(* Logix 5000 project; controller GSC vendor 1 type 14 code 54 rev 19.11; software revision 19.01 *)

TASK MainTask (continuous, watchdog 500 ms) : MainProgram

MODULES
   Local : vendor 1 type 14 code 54 (ICP 0, rev 19.11)
      GSC : vendor 309 type 12 code 5003 (ICP 1, rev 2.1, Output RPI 5 ms)
END_MODULES

TYPE GSCBLOCKSTATUS :   // This shows all blocks that were used by the module
STRUCT
   Read : INT;   // Number of blocks read by the module
   Write : INT;   // Number of blocks written by the module
   Parse : INT;   // Number of blocks parsed by the module
   Err : INT;   // Number of block transfer errors
END_STRUCT
END_TYPE

TYPE GSCCLOCKTYPE :   // Allows read/write of clock value between the module and processor
STRUCT
   Read : BOOL;   // Reads current time from the module
   Write : BOOL;   // Writes current time from the module
   Config : GSCDATETIME;   // Date and time configuration read or written between the module and processor
END_STRUCT
END_TYPE

TYPE GSCCONTROL :   // Ladder send special blocks to request the module to perform the request
STRUCT
   Warmboot : BOOL;   // Performs a warm boot operation on the module (software reset).
   Coldboot : BOOL;   // Performs a cold boot operation on the module (hardware and software reset).
   ConfigDone : BOOL;   // Confirms the module received its configuration from ladder logic
END_STRUCT
END_TYPE

TYPE GSCDATA :   // The following contains the data read in on the port and to be written out the port.
STRUCT
   Port1 : GSCPORTDATA;   // Port 1 data
   Port2 : GSCPORTDATA;   // Port 2 data
END_STRUCT
END_TYPE

TYPE GSCDATETIME :   // Stores the date and time value
STRUCT
   Year : DINT;
   Month : DINT;
   Day : DINT;
   Hour : DINT;
   Minute : DINT;
   Seconds : DINT;
END_STRUCT
END_TYPE

TYPE GSCERRORWORD :   // Bit coded error word for configuration and overflow error for MVI56-GSC module.
STRUCT
   Cfg_type : BOOL;   // Bit 0, type field configuration error
   Cfg_Baud : BOOL;   // Bit 1, baud rate field configuration error
   Cfg_Parity : BOOL;   // Bit 2, parity field configuration error
   Cfg_DataBits : BOOL;   // Bit 3, data bit field configuration error
   Cfg_StopBits : BOOL;   // Bit 4, stop bit field configuration error
   Cfg_Handshake : BOOL;   // Bit 5, handshaking field configuration error
   Cfg_RTermcount : BOOL;   // Bit 6, receive termination character count field configuration error
   Cfg_RPacketLen : BOOL;   // Bit 7, receive packet length field configuration error
   Cfg_RTimeout : BOOL;   // Bit 8, receive message timeout field configuration error
   Cfg_RDelay : BOOL;   // Bit 9, receive intercharacter delay field configuration error
   Cfg_WTimeout : BOOL;   // Bit 10, write message timeout field configuration error
   Resv_Bit11 : BOOL;   // Bit 11
   Resv_Bit12 : BOOL;   // Bit 12
   Resv_Bit13 : BOOL;   // Bit 13
   Resv_Bit14 : BOOL;   // Bit 14
   Err_ROverflow : BOOL;   // Bit 15, receive overflow error
END_STRUCT
END_TYPE

TYPE GSCETHERNET :   // Stores the MVI56E-GSC IP settings
STRUCT
   IP : INT[4];
   Netmask : INT[4];
   Gateway : INT[4];
END_STRUCT
END_TYPE

TYPE GSCETHERNETTYPE :   // Allows read/write Ethernet settings between the module and processor
STRUCT
   Read : BOOL;   // Enable Ethernet configuration transfer from module to processor
   Write : BOOL;   // Enable Ethernet configuration transfer from processor to module
   Config : GSCETHERNET;
END_STRUCT
END_TYPE

TYPE GSCMODULEDEF :   // This defines the complete module tags
STRUCT
   CONFIG : GSCPORTCONFIG;   // Port configuration parameters
   DATA : GSCDATA;   // Port sent and received data
   STATUS : GSCSTATUS;   // Module status data and individual port status
   CONTROL : GSCCONTROL;   // Module control parameters
   UTIL : GSCUTIL;   // Tags used by the module
END_STRUCT
END_TYPE

TYPE GSCPORTCONFIG :   // Shows both ports configuration
STRUCT
   Port1 : GSCPORTCONFIGPARA;   // Port 1 configuration data
   Port2 : GSCPORTCONFIGPARA;   // Port 2 configuration data
END_STRUCT
END_TYPE

TYPE GSCPORTCONFIGPARA :   // The following are the configuration parameters for the port of the MVI56-GSC module.
STRUCT
   Enabled : INT;   // 0=Disable port, 1=Enable port
   Type : INT;   // Type of control used to flush data received on port
   Baudrate : INT;   // Baud rate for communications
   Parity : INT;   // Parity (0=none, 1=odd, 2=even, 3=mark, 4=space)
   DataBits : INT;   // Data bits (5, 6, 7, or 8)
   StopBits : INT;   // Stop bits (1 or 2)
   RTSOn : INT;   // RTS delay before sending data
   RTSOff : INT;   // RTS delay after sending message
   Handshaking : INT;   // Type of Handshaking (0=none, 1=RTSCTS, 2=DTRDSR,3=XONXOFF)
   RTermCnt : INT;   // Number of termination characters for received message for control
   RTermChar : SINT[12];   // Characters for termination control
   RPacketLen : INT;   // Fixed packet length value
   RTimeout : INT;   // Message timeout value for control
   RDelay : INT;   // Intercharacter timeout for control
   WTermCnt : INT;   // Not used
   WTermChar : SINT[12];   // Not used
   WPacketLen : INT;   // Not used
   WTimeout : INT;   // Timeout for sending a message out the port
   Spare : INT;   // Not used
   WMinDelay : INT;   // Minimum delay before transmitting message out port
END_STRUCT
END_TYPE

TYPE GSCPORTDATA :   // Individual port data
STRUCT
   ReadLength : INT;   // The length of character the port is rescieving
   ReadString : SINT[4096];   // Where received data will be displayed
   WriteLength : INT;   // The length of character the port is transmitting
   WDelay : INT;   // Number of milliseconds to wait between each character sent from the port
   WriteString : SINT[4096];   // Where sent data will be placed before it is sent
END_STRUCT
END_TYPE

TYPE GSCPORTSTAT :   // Port status Data
STRUCT
   RxState : INT;   // State of receive task
   RxCharCnt : INT;   // Number of characters received on port
   RxMsgCnt : INT;   // Number of messages received on port
   TxState : INT;   // State of transmit task
   TxCharCnt : INT;   // Number of characters transmitted on port
   TxMsgCnt : INT;   // Number of messages transmitted on port
   ErrorWord : GSCERRORWORD;   // Error/Configuration Word for port
END_STRUCT
END_TYPE

TYPE GSCSTATUS :   // Module Status data
STRUCT
   PassCnt : INT;   // Program cycle counter for module
   Product : INT[2];   // Product code for module (GSC)
   Rev : INT[2];   // Revision level of module's code
   OP : INT[2];   // Operating system version for module
   Run : INT[2];   // Run number for module
   BlockStatus : GSCBLOCKSTATUS;   // Data block transfer statistics
   Port1 : GSCPORTSTAT;   // Status for port1
   Port2 : GSCPORTSTAT;   // Status for port 2
END_STRUCT
END_TYPE

TYPE GSCUTIL :   // Used by the module for block hand shaking
STRUCT
   LastRead : SINT;   // This is used to read the input image from the processor
   LastWrite : SINT;   // This is used to write the output image to the processor
   BackplaneFail : INT;   // This is used to control number of backplane failures before module stops communicating on both gsc ports
   P1WriteLast : INT;   // Port 1 last write data in the array
   P2Writelast : INT;   // Port 2 last data in the array
   P1ArrayIndex : INT;   // This is the index reference within the read or write data array for port1
   P2ArrayIndex : INT;   // This is the index reference within the read or write data array for port 2
   P1RSindex : INT;   // used when more than 200 characters are received on the port 1
   P2RSindex : INT;   // used when more than 200 characters are received on the port 2
   P1Temp1 : INT;   // This temp parameter for port 1 is used to copy SINT to an INT in order to read a vlaue is higher than 127 characters
   P2Temp2 : INT;   // This temp parameter for port 2 is used to copy SINT to an INT in order to read a vlaue is higher than 127 characters
   Scratch1 : INT;   // Used to calculate number of characters read by the port
   Scratch2 : INT;   // Used to calculate number of characters read by the port
END_STRUCT
END_TYPE

ADD_ON_INSTRUCTION AOI56EGSC_OPTIONAL   (* revision 1.1 *)
// MVI56E-GSC Optional Add-On Ethernet/Clock
// Revision note:
// Added viewing capability for the Add_On Instruction
VAR_IN_OUT
   MVI56EGSCEthernet : GSCETHERNETTYPE; {required}   // MVI56E-GSC Rev2 Ethernet Settings
   MVI56EGSCClock : GSCCLOCKTYPE; {required}   // MVI56E-GSC Rev2 Clock Settings
   ReadEthernetMSG : MESSAGE; {required}   // Read Ethernet Settings Message
   WriteEthernetMSG : MESSAGE; {required}   // Write Ethernet Settings Message
   ReadClockMSG : MESSAGE; {required}   // Read Clock Settings Message
   WriteClockMSG : MESSAGE; {required}   // Write Clock Settings Message
END_VAR

ROUTINE Logic   (* ladder *)
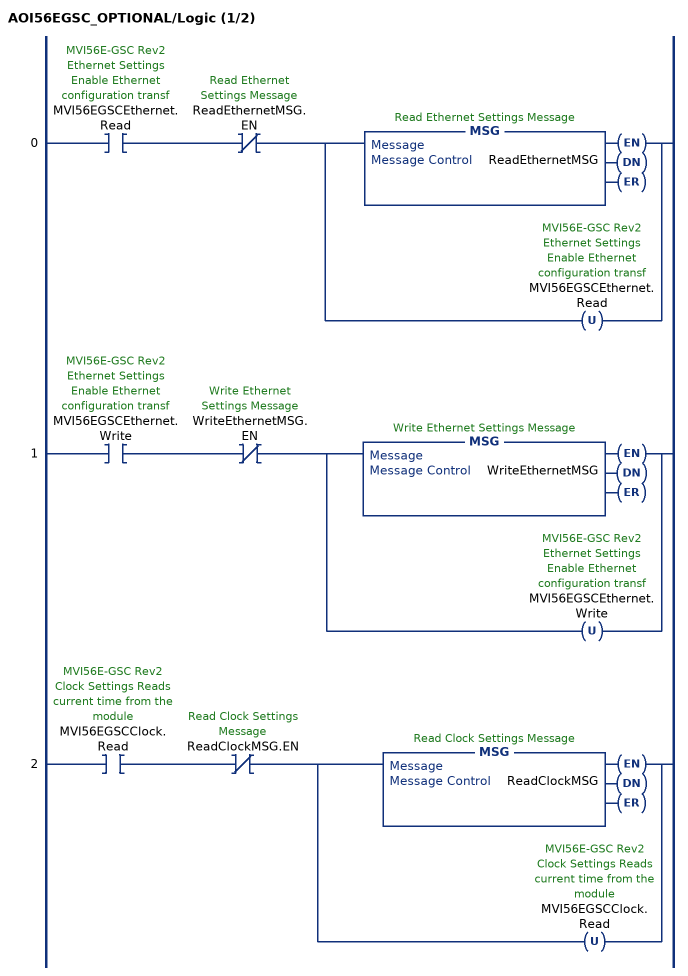
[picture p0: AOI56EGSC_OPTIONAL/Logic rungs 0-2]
   0: XIC(MVI56EGSCEthernet.Read)XIO(ReadEthernetMSG.EN)[MSG(ReadEthernetMSG) ,OTU(MVI56EGSCEthernet.Read) ];
   1: XIC(MVI56EGSCEthernet.Write)XIO(WriteEthernetMSG.EN)[MSG(WriteEthernetMSG) ,OTU(MVI56EGSCEthernet.Write) ];
   2: XIC(MVI56EGSCClock.Read)XIO(ReadClockMSG.EN)[MSG(ReadClockMSG) ,OTU(MVI56EGSCClock.Read) ];
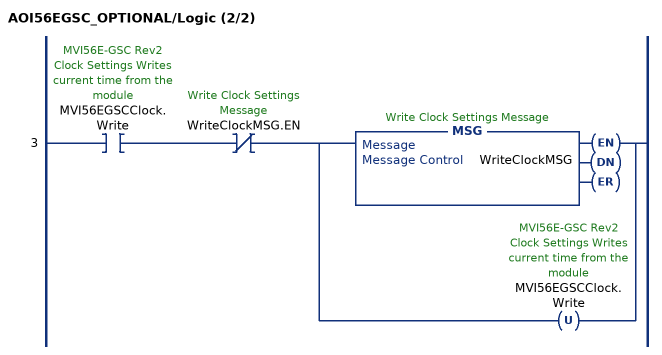
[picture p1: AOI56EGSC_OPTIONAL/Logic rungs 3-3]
   3: XIC(MVI56EGSCClock.Write)XIO(WriteClockMSG.EN)[MSG(WriteClockMSG) ,OTU(MVI56EGSCClock.Write) ];
END_ROUTINE
END_ADD_ON_INSTRUCTION

ADD_ON_INSTRUCTION AOI56GSC   (* revision 1.9, vendor ProSoft Technology Inc., ExecutePrescan *)
// Add-On For MVI56GSC and MVI56EGSC Modules.
// Revision note:
// 7/6/17
// Minor fix to FLL instruction
// 6/7/16
// Confirmed fix regarding 'Copy' length on the GSC.UTIL.PxTempx
// Help:
// 05/09/13
// AOI was fixed so that GSC.UTIL.Backplane.Fail parameter was affecting the intercharacter delay parameter in the module
VAR_IN_OUT
   Connection_Input : SINT[500]; {required}
   Connection_Output : SINT[496]; {required}
   GSC : GSCMODULEDEF; {required}
END_VAR
VAR
   MJFAULTS : DINT[12];
   ONS_Config : BOOL;
END_VAR

ROUTINE Logic   (* ladder *)
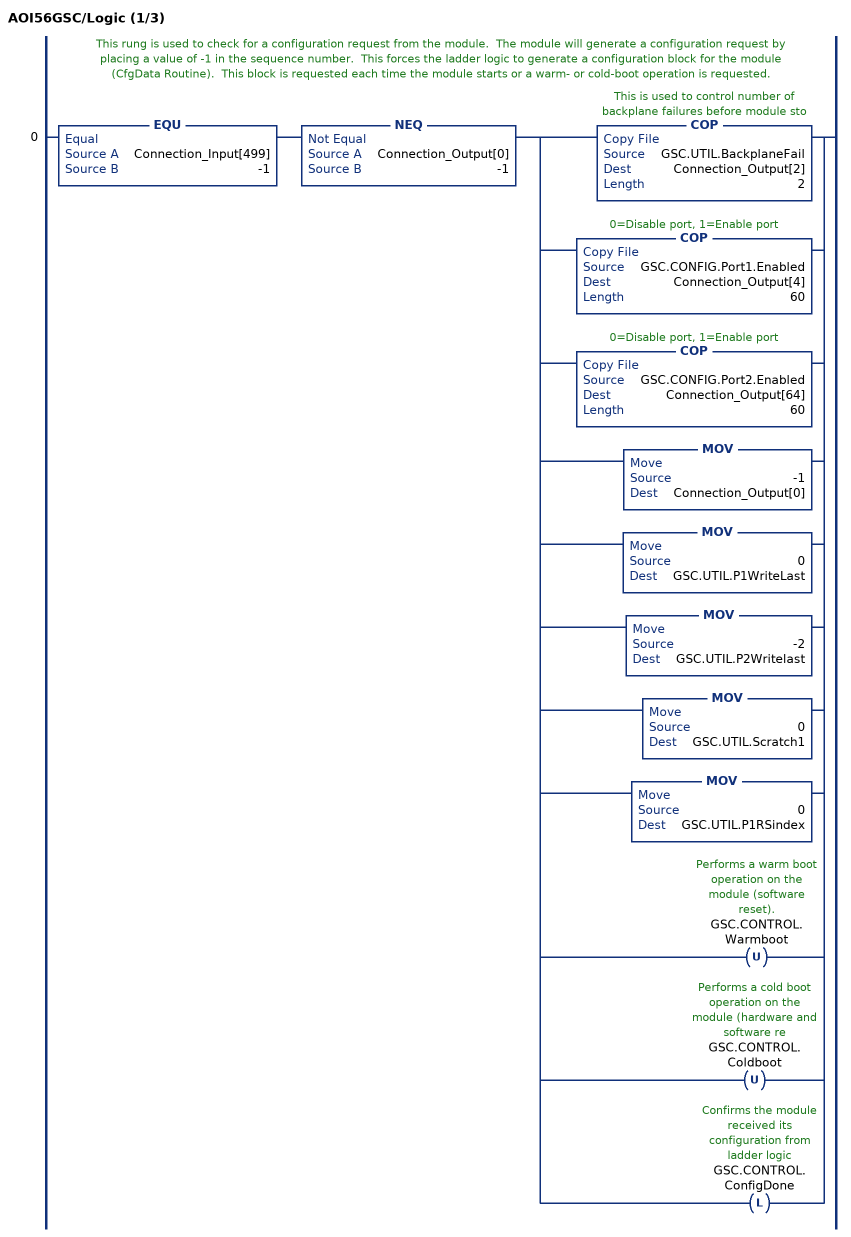
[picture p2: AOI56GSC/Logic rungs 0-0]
   // This rung is used to check for a configuration request from the module.  The module will generate a configuration request by placing a value of -1 in the sequence number.  This forces the ladder logic to generate a configuration block for the module (CfgData Routine).  This block is requested each time the module starts or a warm- or cold-boot operation is requested.
   0: EQU(Connection_Input[499],-1)NEQ(Connection_Output[0],-1)[COP(GSC.UTIL.BackplaneFail,Connection_Output[2],2) ,COP(GSC.CONFIG.Port1.Enabled,Connection_Output[4],60) ,COP(GSC.CONFIG.Port2.Enabled,Connection_Output[64],60) ,MOV(-1,Connection_Output[0]) ,MOV(0,GSC.UTIL.P1WriteLast) ,MOV(-2,GSC.UTIL.P2Writelast) ,MOV(0,GSC.UTIL.Scratch1) ,MOV(0,GSC.UTIL.P1RSindex) ,OTU(GSC.CONTROL.Warmboot) ,OTU(GSC.CONTROL.Coldboot) ,OTL(GSC.CONTROL.ConfigDone) ];
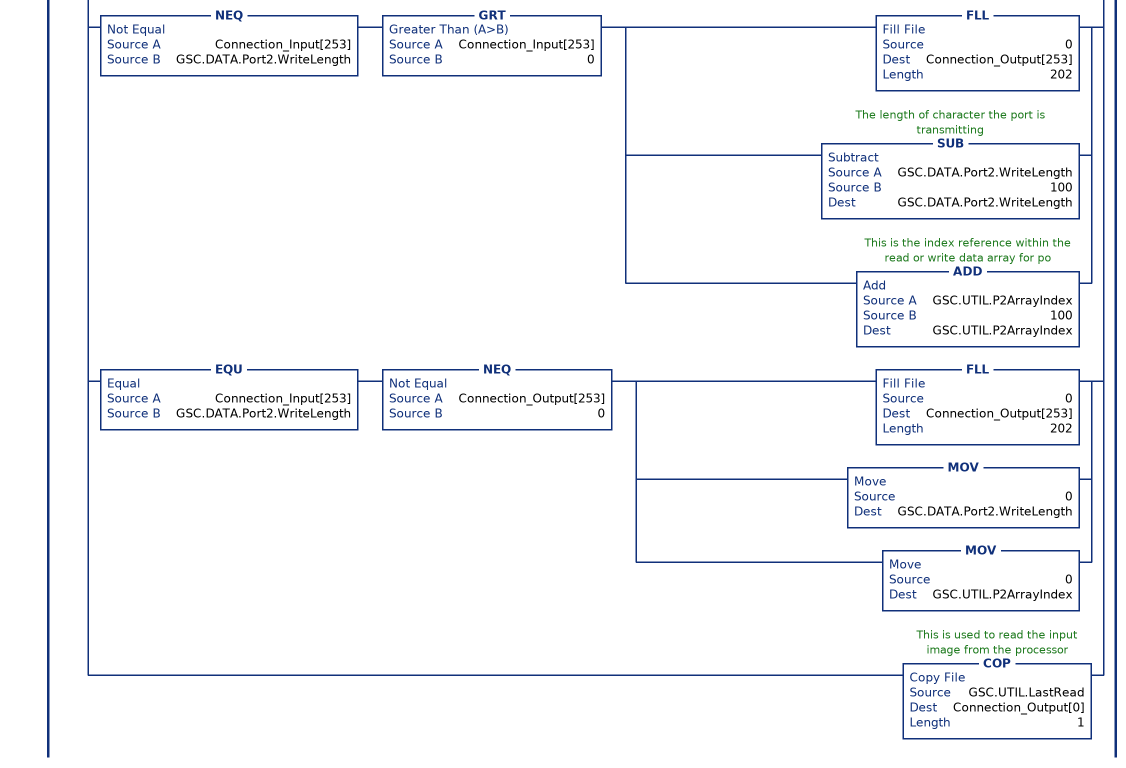
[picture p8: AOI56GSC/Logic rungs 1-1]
   // This rung is executed when a new data block is received from the module.  These blocks will have a sequence number range of 0 to 127.  When a new block is received, the ProcessBlock routine is executed to handle the newly received data.
   1: NEQ(Connection_Input[499],GSC.UTIL.LastRead)NEQ(Connection_Input[499],-1)XIO(GSC.CONTROL.Warmboot)XIO(GSC.CONTROL.Coldboot)[COP(Connection_Input[499],GSC.UTIL.LastRead,1) ,GEQ(GSC.UTIL.LastRead,0) [COP(Connection_Input[210],GSC.STATUS.PassCnt,1) ,COP(Connection_Input[1],GSC.UTIL.P1Temp1,1) ,COP(Connection_Input[251],GSC.UTIL.P2Temp2,1) ,COP(Connection_Input[212],GSC.STATUS.Product[0],8) ,COP(Connection_Input[228],GSC.STATUS.BlockStatus.Read,4) ,COP(Connection_Input[236],GSC.STATUS.Port1.RxState,6) ,COP(Connection_Input[248],GSC.STATUS.Port1.ErrorWord,1) ,COP(Connection_Input[456],GSC.STATUS.Port2.RxState,6) ,COP(Connection_Input[468],GSC.STATUS.Port2.ErrorWord,1) ,EQU(GSC.UTIL.P1Temp1,-1) LES(GSC.UTIL.P1RSindex,20) [COP(Connection_Input[5],GSC.DATA.Port1.ReadString[GSC.UTIL.P1RSindex*200],200) ,ADD(1,GSC.UTIL.P1RSindex,GSC.UTIL.P1RSindex) ,MUL(GSC.UTIL.P1RSindex,200,GSC.UTIL.Scratch1) ] ,GRT(GSC.UTIL.P1Temp1,0) [MOV(0,GSC.DATA.Port1.ReadLength) ,COP(Connection_Input[5],GSC.DATA.Port1.ReadString[GSC.UTIL.P1RSindex*200],200) ,ADD(GSC.UTIL.P1Temp1,GSC.UTIL.Scratch1,GSC.DATA.Port1.ReadLength) ,MOV(0,GSC.UTIL.P1RSindex) ,MOV(0,GSC.UTIL.Scratch1) ] ,EQU(GSC.UTIL.P2Temp2,-1) LES(GSC.UTIL.P2RSindex,20) [COP(Connection_Input[255],GSC.DATA.Port2.ReadString[GSC.UTIL.P2RSindex*200],200) ,ADD(1,GSC.UTIL.P2RSindex,GSC.UTIL.P2RSindex) ,MUL(GSC.UTIL.P2RSindex,200,GSC.UTIL.Scratch2) ] ,GRT(GSC.UTIL.P2Temp2,0) [MOV(0,GSC.DATA.Port2.ReadLength) ,COP(Connection_Input[255],GSC.DATA.Port2.ReadString[GSC.UTIL.P2RSindex*200],200) ,ADD(GSC.UTIL.P2Temp2,GSC.UTIL.Scratch2,GSC.DATA.Port2.ReadLength) ,MOV(0,GSC.UTIL.P2RSindex) ,MOV(0,GSC.UTIL.Scratch2) ] ] ,XIC(GSC.CONTROL.ConfigDone) [FLL(0,Connection_Output[1],495) ,OTU(GSC.CONTROL.ConfigDone) ] ,GRT(GSC.DATA.Port1.WriteLength,100) LEQ(GSC.DATA.Port1.WriteLength,4096) [COP(GSC.DATA.Port1.WriteString[GSC.UTIL.P1ArrayIndex],Connection_Output[5],100) ,MOV(100,Connection_Output[3]) ] ,GRT(GSC.DATA.Port1.WriteLength,0) LEQ(GSC.DATA.Port1.WriteLength,100) [COP(GSC.DATA.Port1.WriteString[GSC.UTIL.P1ArrayIndex],Connection_Output[5],GSC.DATA.Port1.WriteLength) ,COP(GSC.DATA.Port1.WDelay,Connection_Output[1],2) ,MOV(GSC.DATA.Port1.WriteLength,Connection_Output[3]) ] ,NEQ(Connection_Input[3],GSC.DATA.Port1.WriteLength) GRT(Connection_Input[3],0) [FLL(0,Connection_Output[3],202) ,SUB(GSC.DATA.Port1.WriteLength,100,GSC.DATA.Port1.WriteLength) ,ADD(GSC.UTIL.P1ArrayIndex,100,GSC.UTIL.P1ArrayIndex) ] ,EQU(Connection_Input[3],GSC.DATA.Port1.WriteLength) NEQ(Connection_Output[3],0) [FLL(0,Connection_Output[3],202) ,MOV(0,GSC.DATA.Port1.WriteLength) ,MOV(0,GSC.UTIL.P1ArrayIndex) ] ,GRT(GSC.DATA.Port2.WriteLength,100) LEQ(GSC.DATA.Port2.WriteLength,4096) [COP(GSC.DATA.Port2.WriteString[GSC.UTIL.P2ArrayIndex],Connection_Output[255],100) ,MOV(100,Connection_Output[253]) ] ,GRT(GSC.DATA.Port2.WriteLength,0) LEQ(GSC.DATA.Port2.WriteLength,100) [COP(GSC.DATA.Port2.WriteString[GSC.UTIL.P2ArrayIndex],Connection_Output[255],GSC.DATA.Port2.WriteLength) ,COP(GSC.DATA.Port2.WDelay,Connection_Output[251],2) ,MOV(GSC.DATA.Port2.WriteLength,Connection_Output[253]) ] ,NEQ(Connection_Input[253],GSC.DATA.Port2.WriteLength) GRT(Connection_Input[253],0) [FLL(0,Connection_Output[253],202) ,SUB(GSC.DATA.Port2.WriteLength,100,GSC.DATA.Port2.WriteLength) ,ADD(GSC.UTIL.P2ArrayIndex,100,GSC.UTIL.P2ArrayIndex) ] ,EQU(Connection_Input[253],GSC.DATA.Port2.WriteLength) NEQ(Connection_Output[253],0) [FLL(0,Connection_Output[253],202) ,MOV(0,GSC.DATA.Port2.WriteLength) ,MOV(0,GSC.UTIL.P2ArrayIndex) ] ,COP(GSC.UTIL.LastRead,Connection_Output[0],1) ];
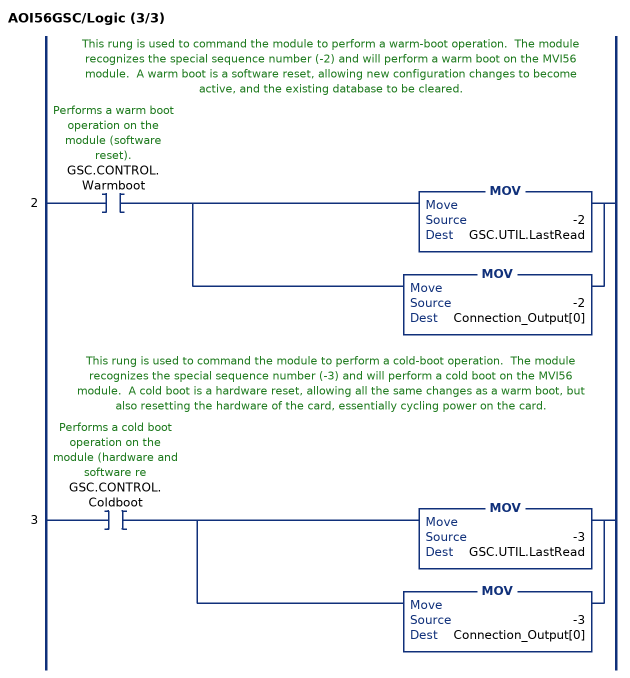
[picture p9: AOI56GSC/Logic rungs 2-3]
   // This rung is used to command the module to perform a warm-boot operation.  The module recognizes the special sequence number (-2) and will perform a warm boot on the MVI56 module.  A warm boot is a software reset, allowing new configuration changes to become active, and the existing database to be cleared.
   2: XIC(GSC.CONTROL.Warmboot)[MOV(-2,GSC.UTIL.LastRead) ,MOV(-2,Connection_Output[0]) ];
   // This rung is used to command the module to perform a cold-boot operation.  The module recognizes the special sequence number (-3) and will perform a cold boot on the MVI56 module.  A cold boot is a hardware reset, allowing all the same changes as a warm boot, but also resetting the hardware of the card, essentially cycling power on the card.
   3: XIC(GSC.CONTROL.Coldboot)[MOV(-3,GSC.UTIL.LastRead) ,MOV(-3,Connection_Output[0]) ];
END_ROUTINE

ROUTINE Prescan   (* ladder *)
// PowerUp
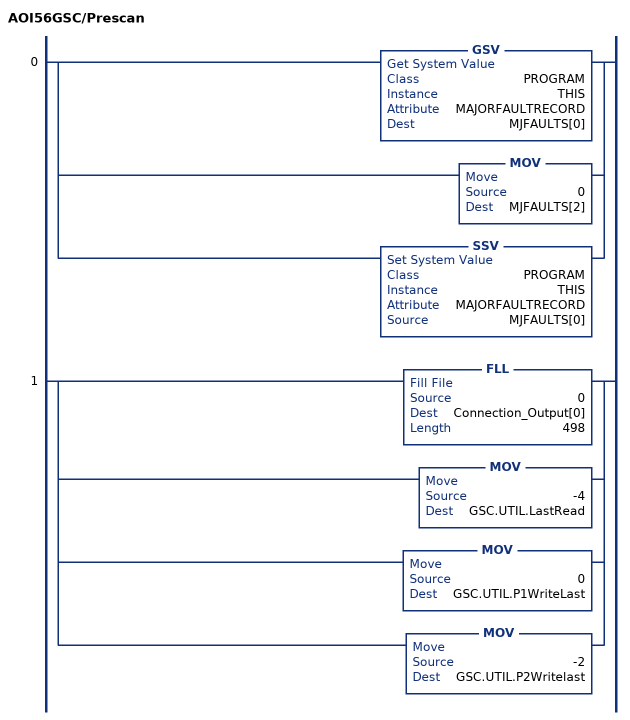
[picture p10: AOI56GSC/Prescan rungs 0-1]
   0: [GSV(PROGRAM,THIS,MAJORFAULTRECORD,MJFAULTS[0]) ,MOV(0,MJFAULTS[2]) ,SSV(PROGRAM,THIS,MAJORFAULTRECORD,MJFAULTS[0]) ];
   1: [FLL(0,Connection_Output[0],498) ,MOV(-4,GSC.UTIL.LastRead) ,MOV(0,GSC.UTIL.P1WriteLast) ,MOV(-2,GSC.UTIL.P2Writelast) ];
END_ROUTINE
END_ADD_ON_INSTRUCTION

VAR_GLOBAL   (* controller tags *)
   AOI56EGSC_OPTIONAL : AOI56EGSC_OPTIONAL;
   AOI56GSC : AOI56GSC;
   GSC : GSCMODULEDEF;
   MVI56EGSCClock : GSCCLOCKTYPE;
   MVI56EGSCEthernet : GSCETHERNETTYPE := (Config.IP[0] := 105, Config.IP[1] := 102, Config.IP[3] := 216, Config.Netmask[0] := 255, Config.Netmask[1] := 255, Config.Netmask[2] := 255, Config.Gateway[0] := 105, Config.Gateway[1] := 102, Config.Gateway[3] := 1);
   ReadClockMSG : MESSAGE;
        MessageParameters(ServiceCode := 16#000e, DestinationTag := MVI56EGSCClock.Config, ...)
   ReadEthernetMSG : MESSAGE;
        MessageParameters(ServiceCode := 16#000e, DestinationTag := MVI56EGSCEthernet.Config, ...)
   WriteClockMSG : MESSAGE;
        MessageParameters(ServiceCode := 16#0010, LocalElement := MVI56EGSCClock.Config, ...)
   WriteEthernetMSG : MESSAGE;
        MessageParameters(ServiceCode := 16#0010, LocalElement := MVI56EGSCEthernet.Config, ...)
END_VAR

PROGRAM MainProgram   (* main routine MainRoutine *)

ROUTINE MainRoutine   (* ladder *)
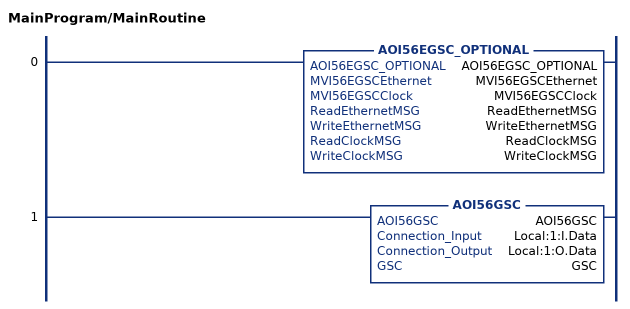
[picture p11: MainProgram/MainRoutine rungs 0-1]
   0: AOI56EGSC_OPTIONAL(AOI56EGSC_OPTIONAL,MVI56EGSCEthernet,MVI56EGSCClock,ReadEthernetMSG,WriteEthernetMSG,ReadClockMSG,WriteClockMSG);
   1: AOI56GSC(AOI56GSC,Local:1:I.Data,Local:1:O.Data,GSC);
END_ROUTINE
END_PROGRAM
